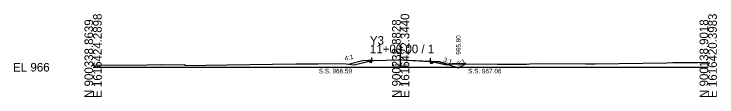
# Model space of a CAD drawing. Extents: x -26 to 203, y -10 to 2017.
# Drawn here: x -25.7 to 202.8, y 990.3 to 1017.3 of the extents above; entities that cross this region are included whole.
import ezdxf

# ---------------------------------------------------------------- set-up
doc = ezdxf.new("R2010")
doc.units = 0
for name, color, linetype in [('Exist Cross Section Cell', 7, 'Continuous'), ('Exist XS Center Line Elevation Label', 7, 'Continuous'), ('Exist XS Ground Line', 7, 'Continuous'), ('Prop XS Dump Level', 7, 'Continuous'), ('Prop XS Earthwork Shape', 7, 'Continuous'), ('Prop XS EOT Tick Mark', 7, 'Continuous'), ('Prop XS Finish Grade', 7, 'Continuous'), ('Prop XS Finish Grade Earthwork', 7, 'Continuous'), ('Prop XS Finish Grade Pavement', 7, 'Continuous'), ('Prop XS Hydro Elevations', 7, 'Continuous'), ('Prop XS Pvmt Edge Slope', 7, 'Continuous'), ('Prop XS Side Slope Text', 7, 'Continuous'), ('Prop XS SS Elevation Text', 7, 'Continuous'), ('Prop XS Subgrade Earthwork', 7, 'Continuous')]:
    doc.layers.add(name, color=color, linetype=linetype)

msp = doc.modelspace()

# ---------------------------------------------------------------- linework, layer by layer
at = {"layer": 'Exist Cross Section Cell'}
for p, q in [((100, 1000), (100, 1007.36)), ((0, 1000), (100, 1000)), ((100, 1000), (200, 1000))]:
    msp.add_line(p, q, dxfattribs=at)
at = {"layer": 'Exist XS Ground Line'}
for p, q in [((43.46, 1000.73), (58.37, 1001.03)), ((58.37, 1001.03), (66.04, 1001.1)), ((66.04, 1001.1), (73.22, 1001.06)), ((73.22, 1001.06), (81.31, 1001.2)), ((81.31, 1001.2), (84.12, 1000.89)), ((84.91, 1000.82), (90.58, 1002.21)), ((90.58, 1002.21), (90.92, 1002.22)), ((90.92, 1002.22), (100, 1002.45)), ((100, 1002.45), (100.34, 1002.45)), ((100.34, 1002.45), (109.74, 1001.95)), ((109.74, 1001.95), (110.04, 1001.89)), ((110.04, 1001.89), (114.89, 1000.82)), ((116.18, 1000.97), (116.72, 1001.09)), ((116.72, 1001.09), (131.44, 1001.01)), ((131.44, 1001.01), (140.88, 1001.01)), ((140.88, 1001.01), (141.95, 1001.13)), ((141.95, 1001.13), (145.88, 1001.18)), ((145.88, 1001.18), (160.26, 1001.14)), ((160.26, 1001.14), (163.26, 1001.07)), ((163.26, 1001.07), (186.54, 1001.48)), ((186.54, 1001.48), (188.5, 1001.5)), ((188.5, 1001.5), (191.55, 1001.52)), ((191.55, 1001.52), (196.62, 1001.58)), ((196.62, 1001.58), (200, 1001.63)), ((0, 1000.73), (2.29, 1000.7)), ((2.29, 1000.7), (17.55, 1000.82)), ((17.55, 1000.82), (22.19, 1000.93)), ((22.19, 1000.93), (22.24, 1000.76)), ((22.24, 1000.76), (29.87, 1000.9)), ((29.87, 1000.9), (29.88, 1000.6)), ((29.88, 1000.6), (43.46, 1000.73)), ((84.12, 1000.89), (84.91, 1000.82)), ((114.89, 1000.82), (116.18, 1000.97))]:
    msp.add_line(p, q, dxfattribs=at)
at = {"layer": 'Prop XS Dump Level'}
for p, q in [((90.59, 1002.22), (100, 1002.45)), ((100, 1002.45), (109.81, 1001.92))]:
    msp.add_line(p, q, dxfattribs=at)
at = {"layer": 'Prop XS Earthwork Shape'}
for points in [[(87.59, 1002.04), (83.33, 1000.98), (84.12, 1000.89), (84.91, 1000.82), (89.66, 1001.99), (89.49, 1002.15)], [(90.59, 1002.22), (90.01, 1001.63), (89.66, 1001.99), (90.58, 1002.21)], [(90.59, 1002.22), (90.01, 1001.63), (90.59, 1001.63)], [(109.74, 1001.95), (110.32, 1001.37), (109.74, 1001.37)], [(110.32, 1001.37), (110.7, 1001.75), (110.04, 1001.89), (109.74, 1001.95)], [(110.7, 1001.75), (114.89, 1000.82), (115.42, 1000.88), (112.74, 1001.78), (110.84, 1001.89)], [(118.66, 999.8), (121.19, 1001.06), (116.72, 1001.09), (116.18, 1000.97), (115.42, 1000.88)]]:
    msp.add_lwpolyline(points, close=True, dxfattribs=at)
at = {"layer": 'Prop XS EOT Tick Mark'}
for p, q in [((90.59, 1002.22), (90.59, 1003.22)), ((109.74, 1001.95), (109.74, 1002.95))]:
    msp.add_line(p, q, dxfattribs=at)
at = {"layer": 'Prop XS Finish Grade'}
for p, q in [((90.59, 1002.22), (89.49, 1002.15)), ((109.74, 1001.95), (110.84, 1001.89))]:
    msp.add_line(p, q, dxfattribs=at)
at = {"layer": 'Prop XS Finish Grade Earthwork'}
for p, q in [((87.59, 1002.04), (83.33, 1000.98)), ((89.49, 1002.15), (87.59, 1002.04)), ((110.84, 1001.89), (112.74, 1001.78)), ((112.74, 1001.78), (118.66, 999.8)), ((118.66, 999.8), (121.19, 1001.06))]:
    msp.add_line(p, q, dxfattribs=at)
at = {"layer": 'Prop XS Finish Grade Pavement'}
for p, q in [((90.59, 1002.22), (100, 1002.45)), ((100, 1002.45), (109.74, 1001.95))]:
    msp.add_line(p, q, dxfattribs=at)
at = {"layer": 'Prop XS Pvmt Edge Slope'}
for p, q in [((90.59, 1002.22), (90.01, 1001.63)), ((109.74, 1001.95), (110.32, 1001.37))]:
    msp.add_line(p, q, dxfattribs=at)
at = {"layer": 'Prop XS Subgrade Earthwork'}
for p, q in [((90.01, 1001.63), (89.49, 1002.15)), ((90.59, 1001.63), (90.01, 1001.63)), ((90.59, 1001.63), (90.59, 1002.22)), ((109.74, 1001.37), (109.74, 1001.95)), ((109.74, 1001.37), (110.32, 1001.37)), ((110.32, 1001.37), (110.84, 1001.89))]:
    msp.add_line(p, q, dxfattribs=at)

# ---------------------------------------------------------------- texts
at = {"layer": 'Exist Cross Section Cell'}
for s, p in [('E 1616424.2898', (2.8, 990)), ('E 1616422.3440', (102.8, 990)), ('E 1616420.3983', (202.8, 990)), ('N 900338.8639', (0, 990)), ('N 900238.8828', (100, 990)), ('N 900138.9018', (200, 990))]:
    msp.add_text(s, height=2.8, rotation=90, dxfattribs=at).set_placement(p)
for s, p in [('Y3', (90, 1007.36)), ('11+00.00 / 1', (90, 1004.56)), ('EL 966', (-26, 998.6))]:
    msp.add_text(s, height=2.8, dxfattribs=at).set_placement(p)
at = {"layer": 'Exist XS Center Line Elevation Label'}
msp.add_text('968.45', height=1.25, dxfattribs=at).set_placement((97.07, 999.82))
at = {"layer": 'Prop XS Dump Level'}
msp.add_text('Eop', height=0.3, rotation=360, dxfattribs=at).set_placement((90.59, 1001.92))
msp.add_text('Eop', height=0.3, dxfattribs=at).set_placement((109.74, 1001.65))
at = {"layer": 'Prop XS Hydro Elevations'}
msp.add_text('965.80', height=1.5, rotation=90, dxfattribs=at).set_placement((119.52, 1004.08))
at = {"layer": 'Prop XS Side Slope Text'}
for s, rotation, p in [('4:1', 14.0362, (81.98, 1002.11)), ('3:1', 341.5651, (113.72, 1001.85)), ('3:1', 26.5651, (118.69, 1000.2))]:
    msp.add_text(s, height=1.5, rotation=rotation, dxfattribs=at).set_placement(p)
at = {"layer": 'Prop XS SS Elevation Text'}
for s, p in [('S.S. 966.59', (73.37, 998)), ('S.S. 967.06', (121.95, 998))]:
    msp.add_text(s, height=1.5, dxfattribs=at).set_placement(p)

doc.saveas('drawing.dxf')
